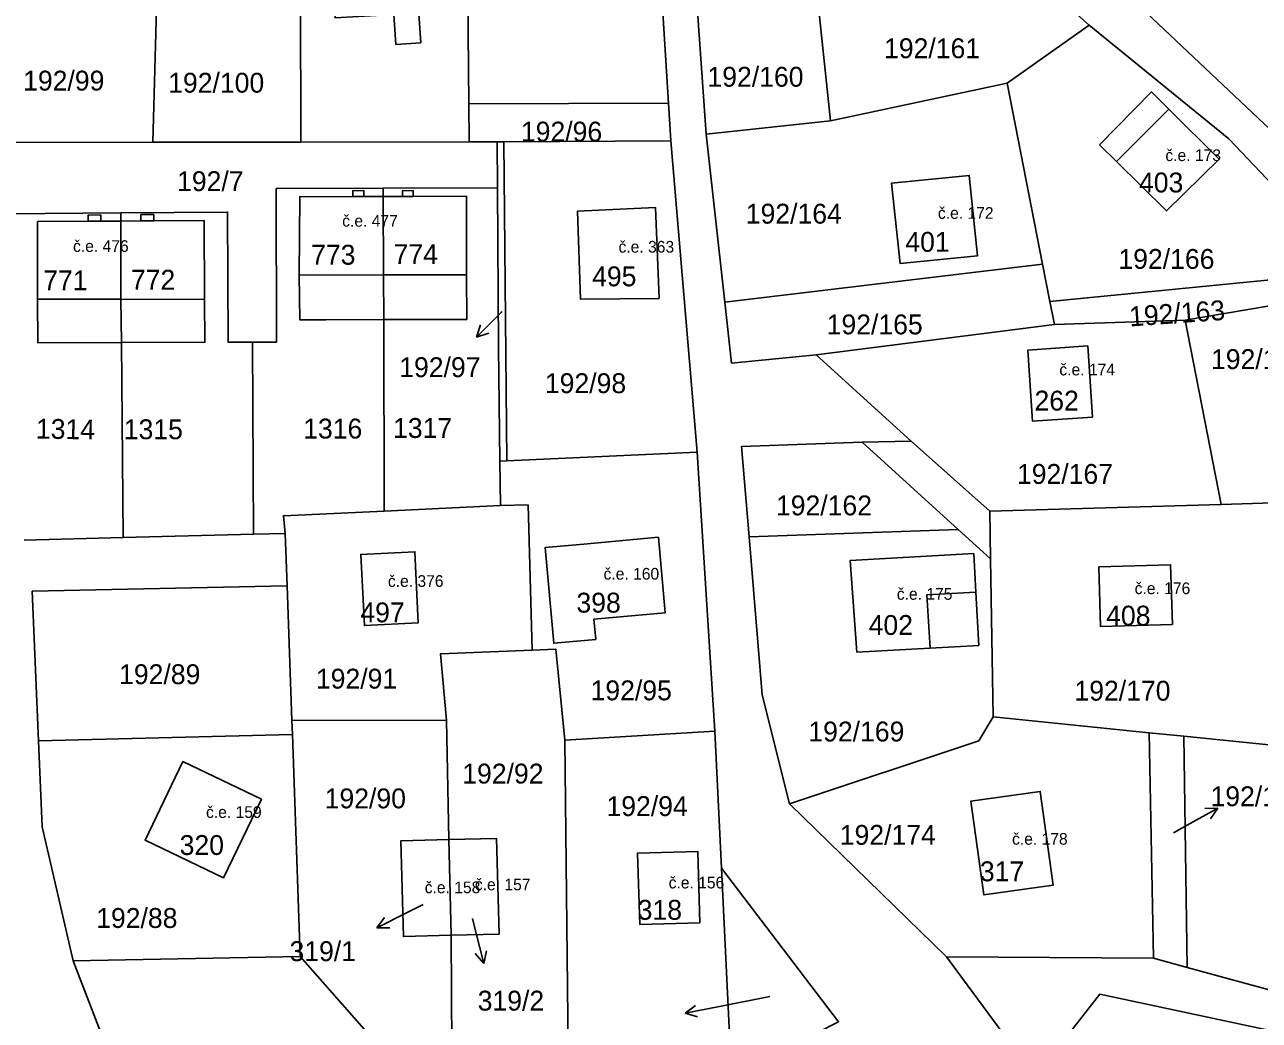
# Model space of a CAD drawing. Extents: x -887272 to -877616, y -1026687 to -1019819.
# Drawn here: x -882394.3 to -882288.7, y -1024193.7 to -1024108.6 of the extents above; entities that cross this region are included whole.
import ezdxf

# ---------------------------------------------------------------- set-up
doc = ezdxf.new("R2010")
doc.units = 0
for name, color, linetype in [('Definiční body', 7, 'Continuous'), ('Hranice parcel', 7, 'Continuous'), ('Parcelní čísla', 7, 'Continuous'), ('Polygon budovy', 7, 'Continuous'), ('Pop  PČ popisy', 7, 'Continuous'), ('Vnitřní kresba', 7, 'Continuous')]:
    doc.layers.add(name, color=color, linetype=linetype)

msp = doc.modelspace()

# ---------------------------------------------------------------- linework, layer by layer
at = {"layer": 'Hranice parcel'}
for p, q in [((-882370.69, -1024118.6), (-882370.74, -1024090.3)), ((-882340.76, -1024090.41), (-882339.24, -1024115.27)), ((-882356.32, -1024115.33), (-882356.54, -1024090.49)), ((-882383.34, -1024118.62), (-882382.62, -1024092.03)), ((-882325.37, -1024116.79), (-882326.44, -1024106.78)), ((-882273.27, -1024131.24), (-882298.33, -1024107.54)), ((-882303.23, -1024108.62), (-882310.26, -1024113.56)), ((-882325.37, -1024116.79), (-882310.26, -1024113.56)), ((-882310.26, -1024113.56), (-882307.23, -1024129.06)), ((-882339.24, -1024115.27), (-882356.32, -1024115.33)), ((-882356.32, -1024115.33), (-882356.29, -1024118.58)), ((-882339.24, -1024115.27), (-882339.04, -1024118.5)), ((-882336.02, -1024117.94), (-882325.37, -1024116.79)), ((-882383.34, -1024118.62), (-882396.14, -1024118.64)), ((-882370.69, -1024118.6), (-882383.34, -1024118.62)), ((-882356.29, -1024118.58), (-882370.69, -1024118.6)), ((-882353.89, -1024118.58), (-882356.29, -1024118.58)), ((-882353.87, -1024122.53), (-882353.89, -1024118.58)), ((-882353.89, -1024118.58), (-882353.31, -1024118.58)), ((-882353.31, -1024118.58), (-882339.04, -1024118.5)), ((-882353.07, -1024145.86), (-882353.31, -1024118.58)), ((-882339.04, -1024118.5), (-882336.77, -1024145.14)), ((-882334.41, -1024132.3), (-882336.02, -1024117.94)), ((-882372.79, -1024122.59), (-882363.66, -1024122.56)), ((-882363.66, -1024122.56), (-882353.87, -1024122.53)), ((-882363.66, -1024123.26), (-882363.66, -1024122.56)), ((-882395.82, -1024124.73), (-882386.09, -1024124.66)), ((-882386.09, -1024125.36), (-882386.09, -1024124.66)), ((-882307.23, -1024129.06), (-882334.41, -1024132.3)), ((-882306.6, -1024132.25), (-882307.23, -1024129.06)), ((-882280.53, -1024129.66), (-882306.6, -1024132.25)), ((-882295.03, -1024133.84), (-882279.12, -1024131.14)), ((-882306.6, -1024132.25), (-882306.22, -1024134.21)), ((-882363.55, -1024150.16), (-882363.6, -1024133.78)), ((-882326.6, -1024136.81), (-882306.22, -1024134.21)), ((-882306.22, -1024134.21), (-882295.03, -1024133.84)), ((-882291.94, -1024149.59), (-882295.03, -1024133.84)), ((-882385.89, -1024152.42), (-882386.04, -1024135.75)), ((-882374.74, -1024152.14), (-882374.83, -1024135.72)), ((-882336.77, -1024145.14), (-882353.07, -1024145.86)), ((-882336.77, -1024145.14), (-882335.28, -1024168.99)), ((-882353.07, -1024145.86), (-882353.66, -1024145.89)), ((-882353.66, -1024145.89), (-882353.61, -1024149.69)), ((-882311.75, -1024150.18), (-882291.94, -1024149.59)), ((-882286.58, -1024149.42), (-882291.94, -1024149.59)), ((-882353.61, -1024149.69), (-882363.55, -1024150.16)), ((-882311.68, -1024154.26), (-882311.75, -1024150.18)), ((-882385.89, -1024152.42), (-882394.36, -1024152.64)), ((-882374.74, -1024152.14), (-882385.89, -1024152.42)), ((-882372.02, -1024152.07), (-882374.74, -1024152.14)), ((-882371.86, -1024156.55), (-882372.02, -1024152.07)), ((-882332.34, -1024152.38), (-882314.45, -1024151.74)), ((-882314.45, -1024151.74), (-882311.68, -1024154.26)), ((-882311.45, -1024167.77), (-882311.68, -1024154.26)), ((-882371.86, -1024156.55), (-882393.69, -1024157.03)), ((-882371.45, -1024168.08), (-882371.86, -1024156.55)), ((-882393.69, -1024157.03), (-882393.14, -1024169.83)), ((-882358.24, -1024168.04), (-882371.45, -1024168.08)), ((-882371.41, -1024169.28), (-882371.45, -1024168.08)), ((-882358.04, -1024178.27), (-882358.24, -1024168.04)), ((-882311.45, -1024167.77), (-882298.11, -1024169.12)), ((-882371.41, -1024169.28), (-882393.14, -1024169.83)), ((-882370.74, -1024188.25), (-882371.41, -1024169.28)), ((-882335.28, -1024168.99), (-882348.11, -1024169.76)), ((-882335.28, -1024168.99), (-882334.7, -1024180.71)), ((-882298.11, -1024169.12), (-882295.13, -1024169.42)), ((-882297.75, -1024188.41), (-882298.11, -1024169.12)), ((-882295.13, -1024169.42), (-882294.85, -1024189.2)), ((-882347.76, -1024199.98), (-882348.11, -1024169.76)), ((-882315.45, -1024188.28), (-882328.87, -1024175.2)), ((-882357.82, -1024186.45), (-882358.04, -1024178.27)), ((-882333.83, -1024198.49), (-882334.7, -1024180.71)), ((-882357.75, -1024201.05), (-882357.82, -1024186.45)), ((-882370.74, -1024188.25), (-882390.17, -1024188.64)), ((-882297.75, -1024188.41), (-882315.45, -1024188.28)), ((-882307.87, -1024198.55), (-882315.45, -1024188.28)), ((-882294.85, -1024189.2), (-882297.75, -1024188.41)), ((-882278.63, -1024193.63), (-882294.85, -1024189.2))]:
    msp.add_line(p, q, dxfattribs=at)
for points in [[(-882325.42, -1024082.75), (-882319.29, -1024094.33), (-882303.23, -1024108.62)], [(-882336.02, -1024117.94), (-882337.81, -1024092.45), (-882335.35, -1024083.33)], [(-882360.43, -1024110.11), (-882360.72, -1024105.96), (-882361.02, -1024101.54), (-882368.16, -1024102.02), (-882367.76, -1024107.97), (-882362.73, -1024107.69), (-882362.56, -1024110.26), (-882360.43, -1024110.11)], [(-882303.23, -1024108.62), (-882291.29, -1024118.32), (-882280.53, -1024129.66)], [(-882302.36, -1024118.83), (-882300.9, -1024120.27), (-882296.63, -1024124.49), (-882292.12, -1024120.06), (-882296.44, -1024115.78), (-882297.91, -1024114.32), (-882302.36, -1024118.83)], [(-882320.14, -1024122.11), (-882319.42, -1024128.99), (-882312.79, -1024128.33), (-882313.5, -1024121.45), (-882320.14, -1024122.11)], [(-882374.83, -1024135.72), (-882372.77, -1024135.71), (-882372.79, -1024122.59)], [(-882363.6, -1024133.78), (-882368.56, -1024133.8), (-882370.77, -1024133.81), (-882370.83, -1024130), (-882370.78, -1024123.28), (-882366.24, -1024123.27), (-882366.25, -1024122.77), (-882365.29, -1024122.76), (-882365.29, -1024123.26), (-882363.66, -1024123.26)], [(-882363.66, -1024123.26), (-882361.98, -1024123.25), (-882362, -1024122.77), (-882361.07, -1024122.75), (-882361.07, -1024123.25), (-882356.53, -1024123.23), (-882356.51, -1024129.95), (-882356.49, -1024133.77), (-882363.6, -1024133.78)], [(-882353.87, -1024122.53), (-882353.79, -1024136.16), (-882353.66, -1024145.89)], [(-882363.6, -1024133.78), (-882363.62, -1024129.97), (-882363.66, -1024123.26)], [(-882340.36, -1024124.19), (-882347.03, -1024124.52), (-882346.75, -1024132.05), (-882340.04, -1024131.97), (-882340.36, -1024124.19)], [(-882386.04, -1024135.75), (-882393.2, -1024135.77), (-882393.22, -1024132.05), (-882393.22, -1024125.41), (-882388.88, -1024125.38), (-882388.88, -1024124.85), (-882387.81, -1024124.84), (-882387.79, -1024125.37), (-882386.09, -1024125.36)], [(-882386.09, -1024124.66), (-882376.96, -1024124.6), (-882376.9, -1024135.72), (-882374.83, -1024135.72)], [(-882386.09, -1024125.36), (-882384.38, -1024125.35), (-882384.37, -1024124.81), (-882383.28, -1024124.81), (-882383.28, -1024125.34), (-882378.96, -1024125.32), (-882378.93, -1024132.06), (-882378.9, -1024135.73), (-882386.04, -1024135.75)], [(-882386.04, -1024135.75), (-882386.08, -1024132.05), (-882386.09, -1024125.36)], [(-882326.6, -1024136.81), (-882333.83, -1024137.51), (-882334.41, -1024132.3)], [(-882311.75, -1024150.18), (-882318.47, -1024144.2), (-882326.6, -1024136.81)], [(-882308.5, -1024136.4), (-882308.08, -1024142.48), (-882302.95, -1024142.12), (-882303.37, -1024136.04), (-882308.5, -1024136.4)], [(-882332.34, -1024152.38), (-882332.98, -1024144.63), (-882322.66, -1024144.28), (-882314.45, -1024151.74)], [(-882363.55, -1024150.16), (-882372.18, -1024150.56), (-882372.02, -1024152.07)], [(-882353.61, -1024149.69), (-882351.25, -1024149.64), (-882350.89, -1024162.07)], [(-882345.46, -1024161.14), (-882345.61, -1024159.42), (-882339.52, -1024158.87), (-882340.1, -1024152.41), (-882346.49, -1024152.99), (-882349.79, -1024153.29), (-882349.05, -1024161.47), (-882345.46, -1024161.14)], [(-882328.87, -1024175.2), (-882331.22, -1024165.89), (-882332.34, -1024152.38)], [(-882360.93, -1024153.64), (-882365.56, -1024153.87), (-882365.25, -1024159.96), (-882360.66, -1024159.73), (-882360.93, -1024153.64)], [(-882313.11, -1024153.8), (-882323.69, -1024154.38), (-882323.12, -1024162.22), (-882316.86, -1024161.9), (-882312.69, -1024161.65), (-882312.93, -1024157.1), (-882313.11, -1024153.8)], [(-882302.42, -1024154.94), (-882302.27, -1024160.04), (-882296.12, -1024159.86), (-882296.27, -1024154.76), (-882302.42, -1024154.94)], [(-882350.89, -1024162.07), (-882358.75, -1024162.38), (-882358.24, -1024168.04)], [(-882348.11, -1024169.76), (-882348.87, -1024161.99), (-882350.89, -1024162.07)], [(-882328.87, -1024175.2), (-882312.69, -1024169.82), (-882311.45, -1024167.77)], [(-882295.13, -1024169.42), (-882287.3, -1024170.21), (-882287.25, -1024168.71)], [(-882393.14, -1024169.83), (-882392.82, -1024177.17), (-882390.17, -1024188.64)], [(-882384.02, -1024178.3), (-882377.3, -1024181.53), (-882374.07, -1024174.82), (-882380.78, -1024171.59), (-882384.02, -1024178.3)], [(-882313.37, -1024174.98), (-882312.24, -1024183), (-882306.31, -1024182.16), (-882307.43, -1024174.15), (-882313.37, -1024174.98)], [(-882358.04, -1024178.27), (-882362.14, -1024178.38), (-882361.92, -1024186.56), (-882357.82, -1024186.45)], [(-882357.82, -1024186.45), (-882353.73, -1024186.34), (-882353.95, -1024178.16), (-882358.04, -1024178.27)], [(-882341.69, -1024185.52), (-882336.54, -1024185.38), (-882336.72, -1024179.28), (-882341.9, -1024179.42), (-882341.69, -1024185.52)], [(-882334.7, -1024180.71), (-882324.68, -1024193.85), (-882333.83, -1024198.49)], [(-882390.17, -1024188.64), (-882382.32, -1024209), (-882378.28, -1024211.6)], [(-882364.57, -1024201.18), (-882365.05, -1024194.74), (-882370.74, -1024188.25)], [(-882287.91, -1024194.55), (-882302.33, -1024191.49), (-882307.87, -1024198.55)]]:
    msp.add_lwpolyline(points, dxfattribs=at)
at = {"layer": 'Polygon budovy'}
for points in [[(-882296.44, -1024115.78), (-882300.9, -1024120.27), (-882296.63, -1024124.49), (-882292.12, -1024120.06)], [(-882313.5, -1024121.45), (-882320.14, -1024122.11), (-882319.42, -1024128.99), (-882312.79, -1024128.33)], [(-882361.98, -1024123.25), (-882363.66, -1024123.26), (-882365.29, -1024123.26), (-882366.24, -1024123.27), (-882370.78, -1024123.28), (-882370.83, -1024130), (-882363.62, -1024129.97), (-882356.51, -1024129.95), (-882356.53, -1024123.23), (-882361.07, -1024123.25)], [(-882347.03, -1024124.52), (-882346.75, -1024132.05), (-882340.04, -1024131.97), (-882340.36, -1024124.19)], [(-882393.22, -1024125.41), (-882393.22, -1024132.05), (-882386.08, -1024132.05), (-882378.93, -1024132.06), (-882378.96, -1024125.32), (-882383.28, -1024125.34), (-882384.38, -1024125.35), (-882386.09, -1024125.36), (-882387.79, -1024125.37), (-882388.88, -1024125.38)], [(-882308.5, -1024136.4), (-882308.08, -1024142.48), (-882302.95, -1024142.12), (-882303.37, -1024136.04)], [(-882349.79, -1024153.29), (-882349.05, -1024161.47), (-882345.46, -1024161.14), (-882345.61, -1024159.42), (-882339.52, -1024158.87), (-882340.1, -1024152.41), (-882346.49, -1024152.99)], [(-882365.25, -1024159.96), (-882360.66, -1024159.73), (-882360.93, -1024153.64), (-882365.56, -1024153.87)], [(-882316.86, -1024161.9), (-882317.12, -1024157.32), (-882312.93, -1024157.1), (-882313.11, -1024153.8), (-882323.69, -1024154.38), (-882323.12, -1024162.22)], [(-882302.42, -1024154.94), (-882302.27, -1024160.04), (-882296.12, -1024159.86), (-882296.27, -1024154.76)], [(-882374.07, -1024174.82), (-882380.78, -1024171.59), (-882384.02, -1024178.3), (-882377.3, -1024181.53)], [(-882306.31, -1024182.16), (-882307.43, -1024174.15), (-882313.37, -1024174.98), (-882312.24, -1024183)], [(-882358.04, -1024178.27), (-882362.14, -1024178.38), (-882361.92, -1024186.56), (-882357.82, -1024186.45)], [(-882358.04, -1024178.27), (-882357.82, -1024186.45), (-882353.73, -1024186.34), (-882353.95, -1024178.16)], [(-882341.9, -1024179.42), (-882341.69, -1024185.52), (-882336.54, -1024185.38), (-882336.72, -1024179.28)]]:
    msp.add_lwpolyline(points, close=True, dxfattribs=at)
at = {"layer": 'Pop  PČ popisy'}
for p, q in [((-882353.55, -1024133.17), (-882355.67, -1024135.29)), ((-882353.48, -1024133.1), (-882353.55, -1024133.17)), ((-882355.67, -1024135.29), (-882355.32, -1024134.23)), ((-882355.67, -1024135.29), (-882354.61, -1024134.94)), ((-882294.85, -1024177.02), (-882292.22, -1024175.57)), ((-882292.22, -1024175.57), (-882293.34, -1024175.61)), ((-882292.22, -1024175.57), (-882292.86, -1024176.49)), ((-882296.03, -1024177.68), (-882294.85, -1024177.02)), ((-882361.53, -1024184.46), (-882364.2, -1024185.82)), ((-882360.23, -1024183.81), (-882361.53, -1024184.46)), ((-882364.2, -1024185.82), (-882363.54, -1024184.92)), ((-882356, -1024185), (-882355.77, -1024185.95)), ((-882364.2, -1024185.82), (-882363.08, -1024185.81)), ((-882355.77, -1024185.95), (-882355.04, -1024188.86)), ((-882355.04, -1024188.86), (-882355.77, -1024188.01)), ((-882355.04, -1024188.86), (-882354.8, -1024187.77)), ((-882330.55, -1024191.69), (-882334.87, -1024192.55)), ((-882337.82, -1024193.12), (-882336.93, -1024192.44)), ((-882334.87, -1024192.55), (-882337.82, -1024193.12)), ((-882337.82, -1024193.12), (-882336.74, -1024193.42))]:
    msp.add_line(p, q, dxfattribs=at)
at = {"layer": 'Vnitřní kresba'}
for p, q in [((-882300.9, -1024120.27), (-882296.44, -1024115.78)), ((-882366.24, -1024123.27), (-882365.29, -1024123.26)), ((-882361.98, -1024123.25), (-882361.07, -1024123.25)), ((-882388.88, -1024125.38), (-882387.79, -1024125.37)), ((-882384.38, -1024125.35), (-882383.28, -1024125.34)), ((-882370.83, -1024130), (-882363.62, -1024129.97)), ((-882363.62, -1024129.97), (-882356.51, -1024129.95)), ((-882386.08, -1024132.05), (-882393.22, -1024132.05)), ((-882378.93, -1024132.06), (-882386.08, -1024132.05)), ((-882318.47, -1024144.2), (-882322.66, -1024144.28)), ((-882312.93, -1024157.1), (-882317.12, -1024157.32)), ((-882317.12, -1024157.32), (-882316.86, -1024161.9))]:
    msp.add_line(p, q, dxfattribs=at)

# ---------------------------------------------------------------- texts
at = {"layer": 'Definiční body'}
for s, p in [('č.e. 173', (-882296.72, -1024120.23)), ('č.e. 172', (-882316.18, -1024125.17)), ('č.e. 477', (-882367.15, -1024125.84)), ('č.e. 476', (-882390.18, -1024128)), ('č.e. 363', (-882343.51, -1024128.06)), ('č.e. 174', (-882305.79, -1024138.56)), ('č.e. 376', (-882363.24, -1024156.65)), ('č.e. 160', (-882344.79, -1024156.03)), ('č.e. 175', (-882319.7, -1024157.75)), ('č.e. 176', (-882299.35, -1024157.27)), ('č.e. 159', (-882378.8, -1024176.41)), ('č.e. 178', (-882309.84, -1024178.7)), ('č.e. 158', (-882360.09, -1024182.85)), ('č.e. 157', (-882355.8, -1024182.6)), ('č.e. 156', (-882339.22, -1024182.44))]:
    msp.add_text(s, height=1, dxfattribs=at).set_placement(p)
at = {"layer": 'Parcelní čísla'}
for s, p in [('192/161', (-882320.79, -1024111.43)), ('192/99', (-882394.45, -1024114.2)), ('192/100', (-882382.04, -1024114.38)), ('192/160', (-882335.9, -1024113.87)), ('192/96', (-882351.86, -1024118.56)), ('192/7', (-882381.28, -1024122.8)), ('403', (-882298.98, -1024122.91)), ('192/164', (-882332.62, -1024125.58)), ('401', (-882318.97, -1024127.99)), ('773', (-882369.81, -1024129.09)), ('774', (-882362.75, -1024129.04)), ('192/166', (-882300.74, -1024129.45)), ('772', (-882385.23, -1024131.23)), ('495', (-882345.77, -1024130.94)), ('771', (-882392.73, -1024131.28)), ('192/165', (-882325.7, -1024135.05)), ('192/97', (-882362.27, -1024138.71)), ('192/168', (-882292.82, -1024138.02)), ('192/98', (-882349.81, -1024140.08)), ('262', (-882307.92, -1024141.57)), ('1317', (-882362.8, -1024143.91)), ('1315', (-882385.84, -1024144.02)), ('1316', (-882370.49, -1024143.96)), ('192/167', (-882309.42, -1024147.84)), ('192/162', (-882330.04, -1024150.53)), ('497', (-882365.6, -1024159.68)), ('398', (-882347.11, -1024158.85)), ('402', (-882322.11, -1024160.76)), ('408', (-882301.79, -1024159.96)), ('192/89', (-882386.24, -1024164.97)), ('192/91', (-882369.4, -1024165.35)), ('192/95', (-882345.9, -1024166.35)), ('192/170', (-882304.5, -1024166.38)), ('192/169', (-882327.27, -1024169.87)), ('192/92', (-882356.88, -1024173.47)), ('192/90', (-882368.65, -1024175.59)), ('192/176', (-882292.86, -1024175.41)), ('192/94', (-882344.54, -1024176.25)), ('192/174', (-882324.58, -1024178.71)), ('320', (-882381.06, -1024179.58)), ('317', (-882312.59, -1024181.83)), ('318', (-882341.87, -1024185.12)), ('192/88', (-882388.2, -1024185.82)), ('319/1', (-882371.66, -1024188.66)), ('319/2', (-882355.56, -1024192.89))]:
    msp.add_text(s, height=1.7, dxfattribs=at).set_placement(p)
for s, rotation, p in [('192/163', 4, (-882299.76, -1024134.38)), ('1314', 359, (-882393.37, -1024143.96))]:
    msp.add_text(s, height=1.7, rotation=rotation, dxfattribs=at).set_placement(p)

doc.saveas('drawing.dxf')
